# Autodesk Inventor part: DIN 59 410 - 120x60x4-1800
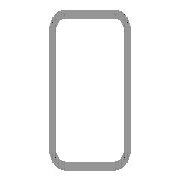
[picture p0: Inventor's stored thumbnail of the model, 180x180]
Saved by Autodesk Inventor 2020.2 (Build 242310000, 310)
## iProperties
Manager: www.cadconsulting.pl
Company: Fabian Stasiak CAD Consulting
IsCustomPart: 1
_CCFamilyMember: 190
_CCFamilyDisplayName: DIN 59410 (Prostokąt) - Rurki stalowe o przekroju prostokątnym formowane na gorąco — Standard DIN 59410 (Prostokąt) został wycofany i zastąpiony przez standard 
_FrameMemberDoc: Frame Member File
_Version: 15.0.0
_GetPNFromCC: 1
Created: 2015-02
Part Number: DIN 59 410 - 120x60x4-1800
Material: Stal, miękka
Description: Rurki stalowe o przekroju prostokątnym formowane na gorąco
Document SubType Name: Modellieren
Standard: DIN
Designer: F.Stasiak
Standards Organization: DIN
Language: pl-PL
Size Designation: 120x60x4
Categories: <MemberInstance><Categories><Category DisplayName="Kształtowniki konstrukcyjne" InternalName="089c4875-fa83-4c05-b084-43b9cc11f5ed" Mnemonic="GRDR"><CategoryPar
Stock Number: 120x60x4
Density: 7.85 g/cm^3
Appearance: Częściowo polerowany
Catalog Web Link: www.expertbooks.pl
G_L: 1800,000 mm
G_W: 60,000 mm
G_H: 120,000 mm
Author: F.Stasiak
Subject: Zbiór ćwiczeń. Autodesk Inventor 2020. Kurs Professional
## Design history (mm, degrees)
node "Płaszczyzna początkowa"
node "Płaszczyzna końcowa"
sketch "Szkic"
  geometry: L1 (-22, 60)-(22, 60); L2 (30, 52)-(30, -52); L3 (22, -60)-(-22, -60); L4 (-30, -52)-(-30, 52); L5 (-44.32, 0)-(44.32, 0) reference; L6 (0, -86.32)-(0, 86.32) reference; L7 (-22, 56)-(22, 56); L8 (26, 52)-(26, -52); L9 (22, -56)-(-22, -56); L10 (-26, -52)-(-26, 52); A1 r 8 centre (-22, 52) between (-22, 60) and (-30, 52); A2 r 8 centre (22, 52) between (30, 52) and (22, 60); A3 r 8 centre (22, -52) between (22, -60) and (30, -52); A4 r 8 centre (-22, -52) between (-30, -52) and (-22, -60); A5 r 4 centre (-22, 52) between (-22, 56) and (-26, 52); A6 r 4 centre (22, 52) between (26, 52) and (22, 56); A7 r 4 centre (22, -52) between (22, -56) and (26, -52); A8 r 4 centre (-22, -52) between (-26, -52) and (-22, -56); 3 further points
  constraints: 16 end point, 16 point on circle, 8 centre point, 8 tangent, 6 point on line, 4 parallel, 3 equal radius, 2 perpendicular, 1 horizontal, 7 other
  dimensions: "b" = 60 distance of point (-30, 60) point (30, 60); "ParH" = 120 distance of point (30, 60) point (30, -60); "msp_r" = 8 radius of A1 (= 2 x ParT); "d8" = 30 distance between parallel lines of L4 L6 (= 0.5 x b); "d9" = 60 distance between parallel lines of L5 L1 (= 0.5 x ParH); "d10" = 4 distance between parallel lines of L4 L10 (= ParT)
extrude "Bryła" new body sketch "Szkic" taper "d4" = 0 deg; stored distance "NLG" = 10
node "Driven Length"
  sketch "Sketch2"
    geometry: L1 (0, 0)-(10, 0) reference
    constraints: 2 end point, 1 horizontal
  workplane "Work Plane3"
  sketch "Sketch3"
    geometry: L1 (-2, 0)-(12, 0) reference; L2 (-2, 1800)-(12, 1800) reference
    dimensions: "d14" = 1800 distance between parallel lines of L1 L2 (derived)
body "Solid1"
other parameters: "ParT" = 4, "G_OFFSET_START" = 0 [user parameter; used in 1 equation term], "G_OFFSET_END" = 0 [user parameter; used in 1 equation term], "d11" = 0 (computed from G_OFFSET_START), "G_L" = 1800 (= d14) [user parameter], "d13" = 90 deg
